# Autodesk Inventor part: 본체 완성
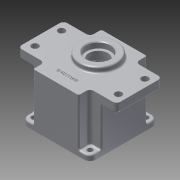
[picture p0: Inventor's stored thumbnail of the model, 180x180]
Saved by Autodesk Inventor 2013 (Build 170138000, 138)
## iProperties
Created: 2015-07
Part Number: 본체 완성
Material: 알루미늄 6061
Document SubType Name: Modeling
Designer: user
Density: 2.71 g/cm^3
Mass: 706.146 g
Surface Area: 672.799 cm^2
Volume: 260.571 cm^3
Author: user
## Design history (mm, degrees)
sketch "스케치1"
  geometry: L1 (-65, -30)-(65, -30); L2 (65, -30)-(65, 30); L3 (65, 30)-(-65, 30); L4 (-65, 30)-(-65, -30); L5 (-65, -30)-(65, 30); L6 (65, -30)-(-65, 30); 1 further point
  constraints: 12 end point, 2 midpoint, 2 parallel, 1 horizontal, 1 perpendicular
  dimensions: "d0" = 130 distance of L3.end L2.end; "d1" = 60 distance of L2.end L1.end
extrude "돌출1" new body sketch "스케치1" distance "d2" = 12; taper "d3" = 0 deg
sketch "스케치2"
  geometry: L1 (-30, -45)-(30, -45); L2 (30, -45)-(30, 45); L3 (30, 45)-(-30, 45); L4 (-30, 45)-(-30, -45); L5 (-30, -45)-(30, 45); L6 (30, -45)-(-30, 45); 1 further point
  constraints: 12 end point, 2 midpoint, 2 parallel, 1 horizontal, 1 perpendicular
  dimensions: "d4" = 60 distance of L3.end L2.end; "d5" = 90 distance of L2.end L1.end
extrude "돌출2" join sketch "스케치2" distance "d6" = 70; taper "d7" = 0 deg
sketch "스케치3"
  geometry: L1 (-30, -45)-(30, -45) reference; L2 (30, -45)-(30, 45) reference; L3 (30, 45)-(-30, 45) reference; L4 (-30, 45)-(-30, -45) reference; L5 (-45, -45)-(45, -45); L6 (45, -45)-(45, 45); L7 (45, 45)-(-45, 45); L8 (-45, 45)-(-45, -45); L9 (-45, -45)-(45, 45); L10 (45, -45)-(-45, 45); 1 further point
  constraints: 12 end point, 2 midpoint, 2 parallel, 1 horizontal, 1 perpendicular
  dimensions: "d8" = 90 distance of L7.end L6.end; "d9" = 90 distance of L6.end L5.end
extrude "돌출3" join sketch "스케치3" distance "d10" = 7; taper "d11" = 0 deg
fillet "모깎기1" dims "d12" = 5
fillet "모깎기2" dims "d13" = 8
sketch "스케치4"
  geometry: L1 (-45, -30)-(45, -30); L2 (45, -30)-(45, 30); L3 (45, 30)-(-45, 30); L4 (-45, 30)-(-45, -30); L5 (-45, -30)-(45, 30); L6 (45, -30)-(-45, 30); 1 further point
  constraints: 12 end point, 2 midpoint, 2 parallel, 1 horizontal, 1 perpendicular
  dimensions: "d14" = 90 distance of L3.end L2.end; "d15" = 60 distance of L2.end L1.end
extrude "돌출4" join sketch "스케치4" distance "d16" = 70; taper "d17" = 0 deg
fillet "모깎기3" dims "d18" = 5
fillet "모깎기4" dims "d19" = 2
fillet "모깎기5" dims "d20" = 2
fillet "모깎기6" dims "d21" = 2
sketch "스케치5"
  geometry: L1 (-37, -37)-(37, -37); L2 (37, -37)-(37, 37); L3 (37, 37)-(-37, 37); L4 (-37, 37)-(-37, -37); L5 (-37, -37)-(37, 37); L6 (37, -37)-(-37, 37); C1 r 3.5 at (37, 37); C2 r 3.5 at (37, -37); C3 r 3.5 at (-37, 37); C4 r 3.5 at (-37, -37); 1 further point
  constraints: 12 end point, 4 centre point, 4 coincident, 2 midpoint, 2 parallel, 1 horizontal, 1 perpendicular
  dimensions: "d22" = 74 distance of L3.end L2.end; "d23" = 74 distance of L2.end L1.end; "d24" = 7 diameter of C1; "d25" = 7 diameter of C2; "d26" = 7 diameter of C3; "d27" = 7 diameter of C4
extrude "돌출5" cut sketch "스케치5" distance "d28" = 70; taper "d29" = 0 deg
sketch "스케치6"
  geometry: L1 (-55, -17.5)-(55, -17.5); L2 (55, -17.5)-(55, 17.5); L3 (55, 17.5)-(-55, 17.5); L4 (-55, 17.5)-(-55, -17.5); L5 (-55, -17.5)-(55, 17.5); L6 (55, -17.5)-(-55, 17.5); C1 r 4.5 at (55, 17.5); C2 r 4.5 at (55, -17.5); C3 r 4.5 at (-55, -17.5); C4 r 4.5 at (-55, 17.5); 1 further point
  constraints: 12 end point, 4 centre point, 4 coincident, 2 midpoint, 2 parallel, 1 horizontal, 1 perpendicular
  dimensions: "d30" = 110 distance of L3.end L2.end; "d31" = 35 distance of L2.end L1.end; "d32" = 9 diameter of C1; "d33" = 9 diameter of C2; "d34" = 9 diameter of C3; "d35" = 9 diameter of C4
extrude "돌출6" cut sketch "스케치6" distance "d36" = 20; taper "d37" = 0 deg
sketch "스케치7"
  geometry: C1 r 40 at (0, 0); 1 further point
  constraints: 1 centre point, 1 coincident
  dimensions: "d38" = 80 diameter of C1
extrude "돌출7" cut sketch "스케치7" distance "d39" = 9; taper "d40" = 0 deg
sketch "스케치8"
  geometry: C1 r 40 at (0, 0) reference; C2 r 39 at (0, 0)
  constraints: 1 centre point, 1 coincident
  dimensions: "d41" = 78 diameter of C2
extrude "돌출8" cut sketch "스케치8" distance "d42" = 52; taper "d43" = 0 deg
sketch "스케치10"
  geometry: L1 (-45, -70)-(-45, 0) reference; L2 (-45, 0)-(45, 0) reference; L3 (45, 0)-(45, -70) reference; L4 (45, -70)-(40, -70) reference; L5 (40, -70)-(40, -61) reference; L6 (40, -61)-(39, -61) reference; L7 (39, -61)-(39, -9) reference; L8 (39, -9)-(-39, -9) reference; L9 (-39, -9)-(-39, -61) reference; L10 (-39, -61)-(-40, -61) reference; L11 (-40, -61)-(-40, -70) reference; L12 (-40, -70)-(-45, -70) reference; L13 (0, 0)-(11, 0); L14 (0, 0)-(-20, 0); L15 (11, 0)-(11, -16); L16 (11, 0)-(11, 7); L17 (-20, 0)-(-20, -16); L18 (27, 7)-(36, 7); L19 (36, 7)-(36, -5); L20 (36, -5)-(31.5, -5); L21 (31.5, -5)-(31.5, -16); L22 (31.5, -16)-(28.5, -16); L23 (28.5, -16)-(28.5, -6); L24 (28.5, -6)-(23.5, -6); L25 (23.5, -6)-(23.5, -1); L26 (23.5, -1)-(27, -1); L27 (27, -1)-(27, 7); L28 (-20, -16)-(-6, -16); L29 (-6, -16)-(-6, 0); L30 (-6, 0)-(-20, 0)
  constraints: 36 end point, 7 parallel, 7 perpendicular, 3 point on line, 2 collinear
  dimensions: "d44" = 11 distance of L13.start L13.end; "d45" = 20 distance of L13.start L14.end; "d46" = 16 distance of L13.end L15.end; "d47" = 7 distance of L13.end L16.end; "d48" = 16 distance of L14.end L17.end; "d49" = 32 diameter of L27 L15; "d50" = 25 diameter of L25 L15; "d51" = 35 diameter of L23 L15; "d52" = 41 diameter of L21 L15; "d53" = 50 diameter of L19 L15; "d54" = 7 distance between parallel lines of L2 L18; "d55" = 7 distance between parallel lines of L8 L22; "d56" = 8 distance of L26.end L18.start; "d57" = 5 distance of L24.end L25.end; "d58" = 4 distance between parallel lines of L8 L20; "d59" = 14 distance of L17.end L28.end
  node "절단 모서리 투영1"
revolve "회전1" stored, may be unused: angle "d60" = 90 deg
revolve "회전2" stored, may be unused: angle "d61" = 90 deg
sketch "스케치11"
  geometry: C1 r 17.5 at (0, 0); C2 r 12.5 at (0, 0); A1 r 17.5 centre (0, 0) between (2.777, -17.278) and (-2.777, -17.278) reference; A2 r 14 centre (0, -31) between (2.777, -17.278) and (-2.777, -17.278) reference; A3 r 20.5 centre (0, 0) between (7.402, -19.117) and (-7.402, -19.117) reference; 1 further point
  constraints: 2 centre point, 2 coincident, 1 concentric
  dimensions: "d62" = 25 diameter of C2
extrude "돌출10" cut sketch "스케치11" distance "d65" = 10; taper "d66" = 0 deg
extrude "돌출11" cut sketch "스케치11" distance "d67" = 50; taper "d68" = 0 deg
fillet "모깎기7" dims "d69" = 2
chamfer "모따기1" distance "d70" = 1; stored, may be unused: second distance "d71" = 2, angle "d72" = 45 deg
hole "구멍1" diameter "d75" = 19; stored, may be unused: countersink angle "d79" = 90 deg, drill point angle "d81" = 0 deg; dims "d73" = 10, "d74" = 10, "d76" = 6, "d77" = 22, "d78" = 7, "d80" = 8
chamfer "모따기2" distance "d82" = 1; stored, may be unused: second distance "d83" = 2, angle "d84" = 45 deg
fillet "모깎기8" dims "d85" = 2
fillet "모깎기10" dims "d121" = 2, "d122" = 3
node "작업 평면2"
sketch "스케치12"
  geometry: L1 (45, 28)-(45, -28) reference; L2 (43, -30)-(35, -30) reference; L3 (30, -35)-(30, -43) reference; L4 (28, -45)-(-28, -45) reference; L5 (-30, -43)-(-30, -35) reference; L6 (-35, -30)-(-43, -30) reference; L7 (-45, -28)-(-45, 28) reference; L8 (-43, 30)-(-35, 30) reference; L9 (-30, 35)-(-30, 43) reference; L10 (-28, 45)-(28, 45) reference; L11 (30, 43)-(30, 35) reference; L12 (35, 30)-(43, 30) reference; L13 (0, 0)-(24.749, 24.749); L14 (0, 0)-(35, 0); L15 (24.603, 30.26)-(21.758, 27.415); L16 (30.26, 24.603)-(27.415, 21.758); L17 (5.657, 0)-(4.581, -1.076); C1 r 40 at (0, 0) reference; A1 r 39 centre (0, 0) between (30.26, 24.603) and (24.603, 30.26) reference; A2 r 2 centre (43, 28) between (45, 28) and (43, 30) reference; A3 r 2 centre (43, -28) between (43, -30) and (45, -28) reference; A4 r 5 centre (35, -35) between (35, -30) and (30, -35) reference; A5 r 2 centre (28, -43) between (28, -45) and (30, -43) reference; A6 r 2 centre (-28, -43) between (-30, -43) and (-28, -45) reference; A7 r 5 centre (-35, -35) between (-30, -35) and (-35, -30) reference; A8 r 2 centre (-43, -28) between (-45, -28) and (-43, -30) reference; A9 r 2 centre (-43, 28) between (-43, 30) and (-45, 28) reference; A10 r 5 centre (-35, 35) between (-35, 30) and (-30, 35) reference; A11 r 2 centre (-28, 43) between (-28, 45) and (-30, 43) reference; A12 r 2 centre (28, 43) between (30, 43) and (28, 45) reference; A13 r 5 centre (35, 35) between (30, 35) and (35, 30) reference; A14 r 35 centre (0, 0) between (24.749, 24.749) and (27.415, 21.758); A15 r 4 centre (24.749, 24.749) between (21.92, 27.577) and (27.577, 21.92); 2 further points
  constraints: 10 end point, 7 point on circle, 3 coincident, 3 point on line, 2 centre point, 2 parallel, 2 tangent, 1 equal length, 1 horizontal, 3 other
  dimensions: "d90" = 70 diameter of A14; "d91" = 45 deg angle of L14 L13; "d92" = 8 diameter of A15; "d95" = 4 distance from line of A1.centre L16
extrude "돌출12" join sketch "스케치12" distance "d96" = 55; taper "d97" = 0 deg
fillet "모깎기12" dims "d101" = 3.5
fillet "모깎기13" dims "d105" = 2
hole "구멍2" diameter "d108" = 3.459; stored, may be unused: countersink angle "d112" = 90 deg, drill point angle "d114" = 118 deg; dims "d106" = 10, "d107" = 10, "d109" = 12, "d110" = 22, "d111" = 7, "d113" = 15
sketch "스케치13"
  geometry: L1 (-28, -45)-(28, -45) reference; L2 (-30, -35)-(-30, -43) reference; L3 (0, -45)-(0, -30); 2 further points
  constraints: 2 end point, 1 coincident, 1 midpoint, 1 parallel, 1 other
  dimensions: "d118" = 15 distance of L3.start L3.end
feature "엠보싱1" sketch "스케치13" dims "d119" = 0.5, "d120" = 0
node "작업 평면3"
sketch "스케치14"
  geometry: C1 r 15.7 at (0, 0) reference; C2 r 16 at (0, 0); 1 further point
  constraints: 1 centre point, 1 coincident
  dimensions: "d123" = 32 diameter of C2
extrude "돌출13" cut sketch "스케치14" distance "d124" = 1; taper "d125" = 0 deg
sketch "스케치15"
  geometry: C1 r 15.7 at (0, 0) reference; C2 r 12.5 at (0, 0) reference; C3 r 16 at (0, 0); 1 further point
  constraints: 1 centre point, 1 coincident
  dimensions: "d126" = 32 diameter of C3
extrude "돌출14" cut sketch "스케치15" distance "d127" = 1; taper "d128" = 0 deg
fillet "모깎기14" dims "d129" = 0.3
node "솔리드1"
pattern_circular "원형 패턴1" dims angle "d99" = 360 deg
pattern_circular "원형 패턴2" dims angle "d103" = 360 deg
pattern_circular "원형 패턴3" dims angle "d116" = 360 deg
node "절단 모서리 투영2"
other parameters: "d89" = -9, "d93" = 4, "d94" = 8
